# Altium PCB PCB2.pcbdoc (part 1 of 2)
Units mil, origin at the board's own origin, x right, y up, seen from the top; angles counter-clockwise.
Board outline 4275 x 4381.77 mil, 2 copper layers (Top Layer, Bottom Layer); 56 components, 70 nets, 265 pads, 133 vias.
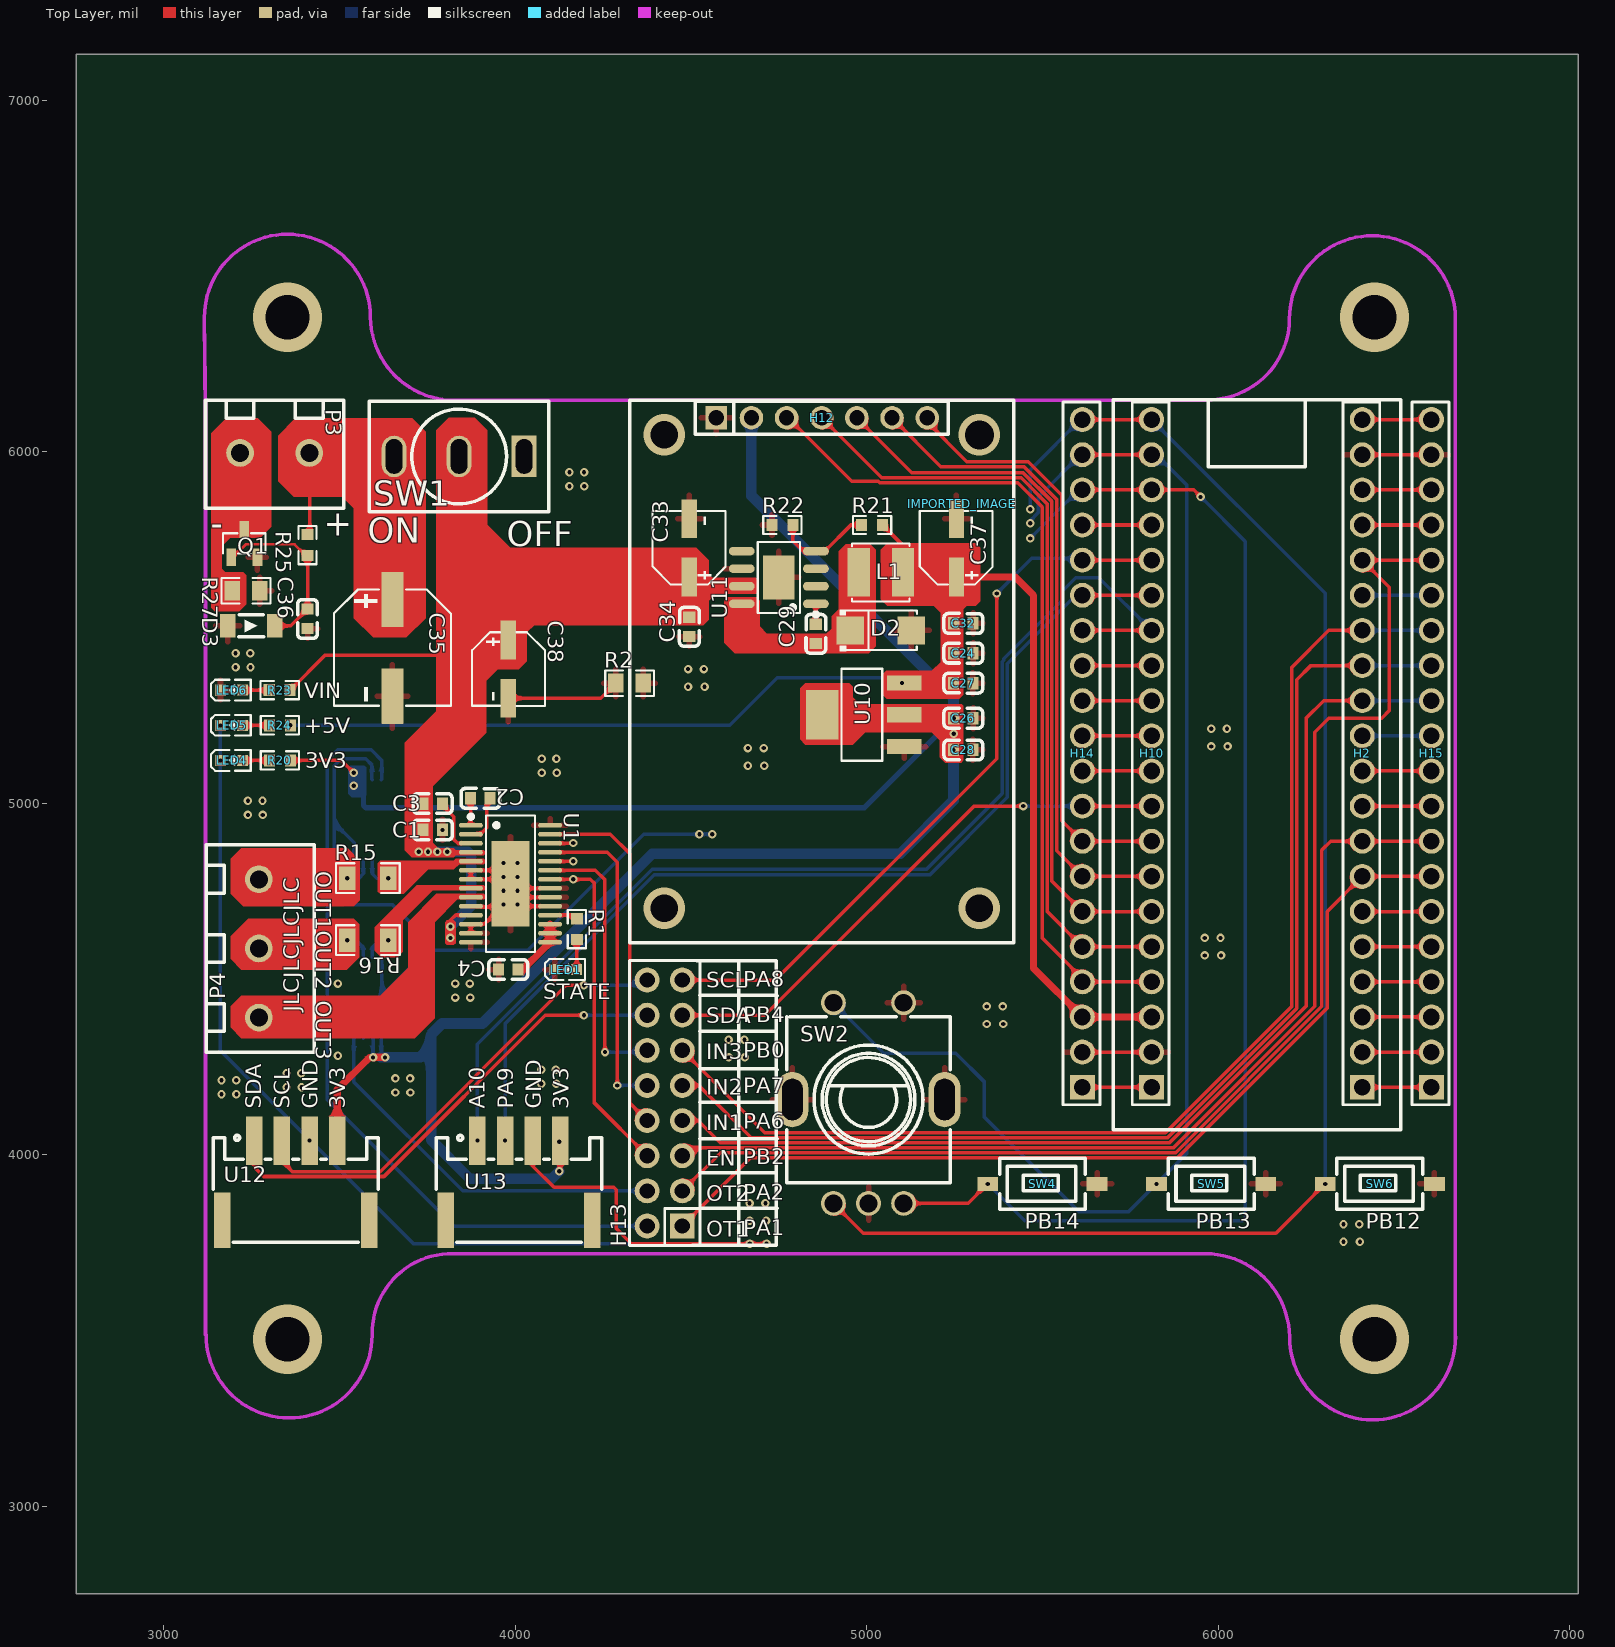
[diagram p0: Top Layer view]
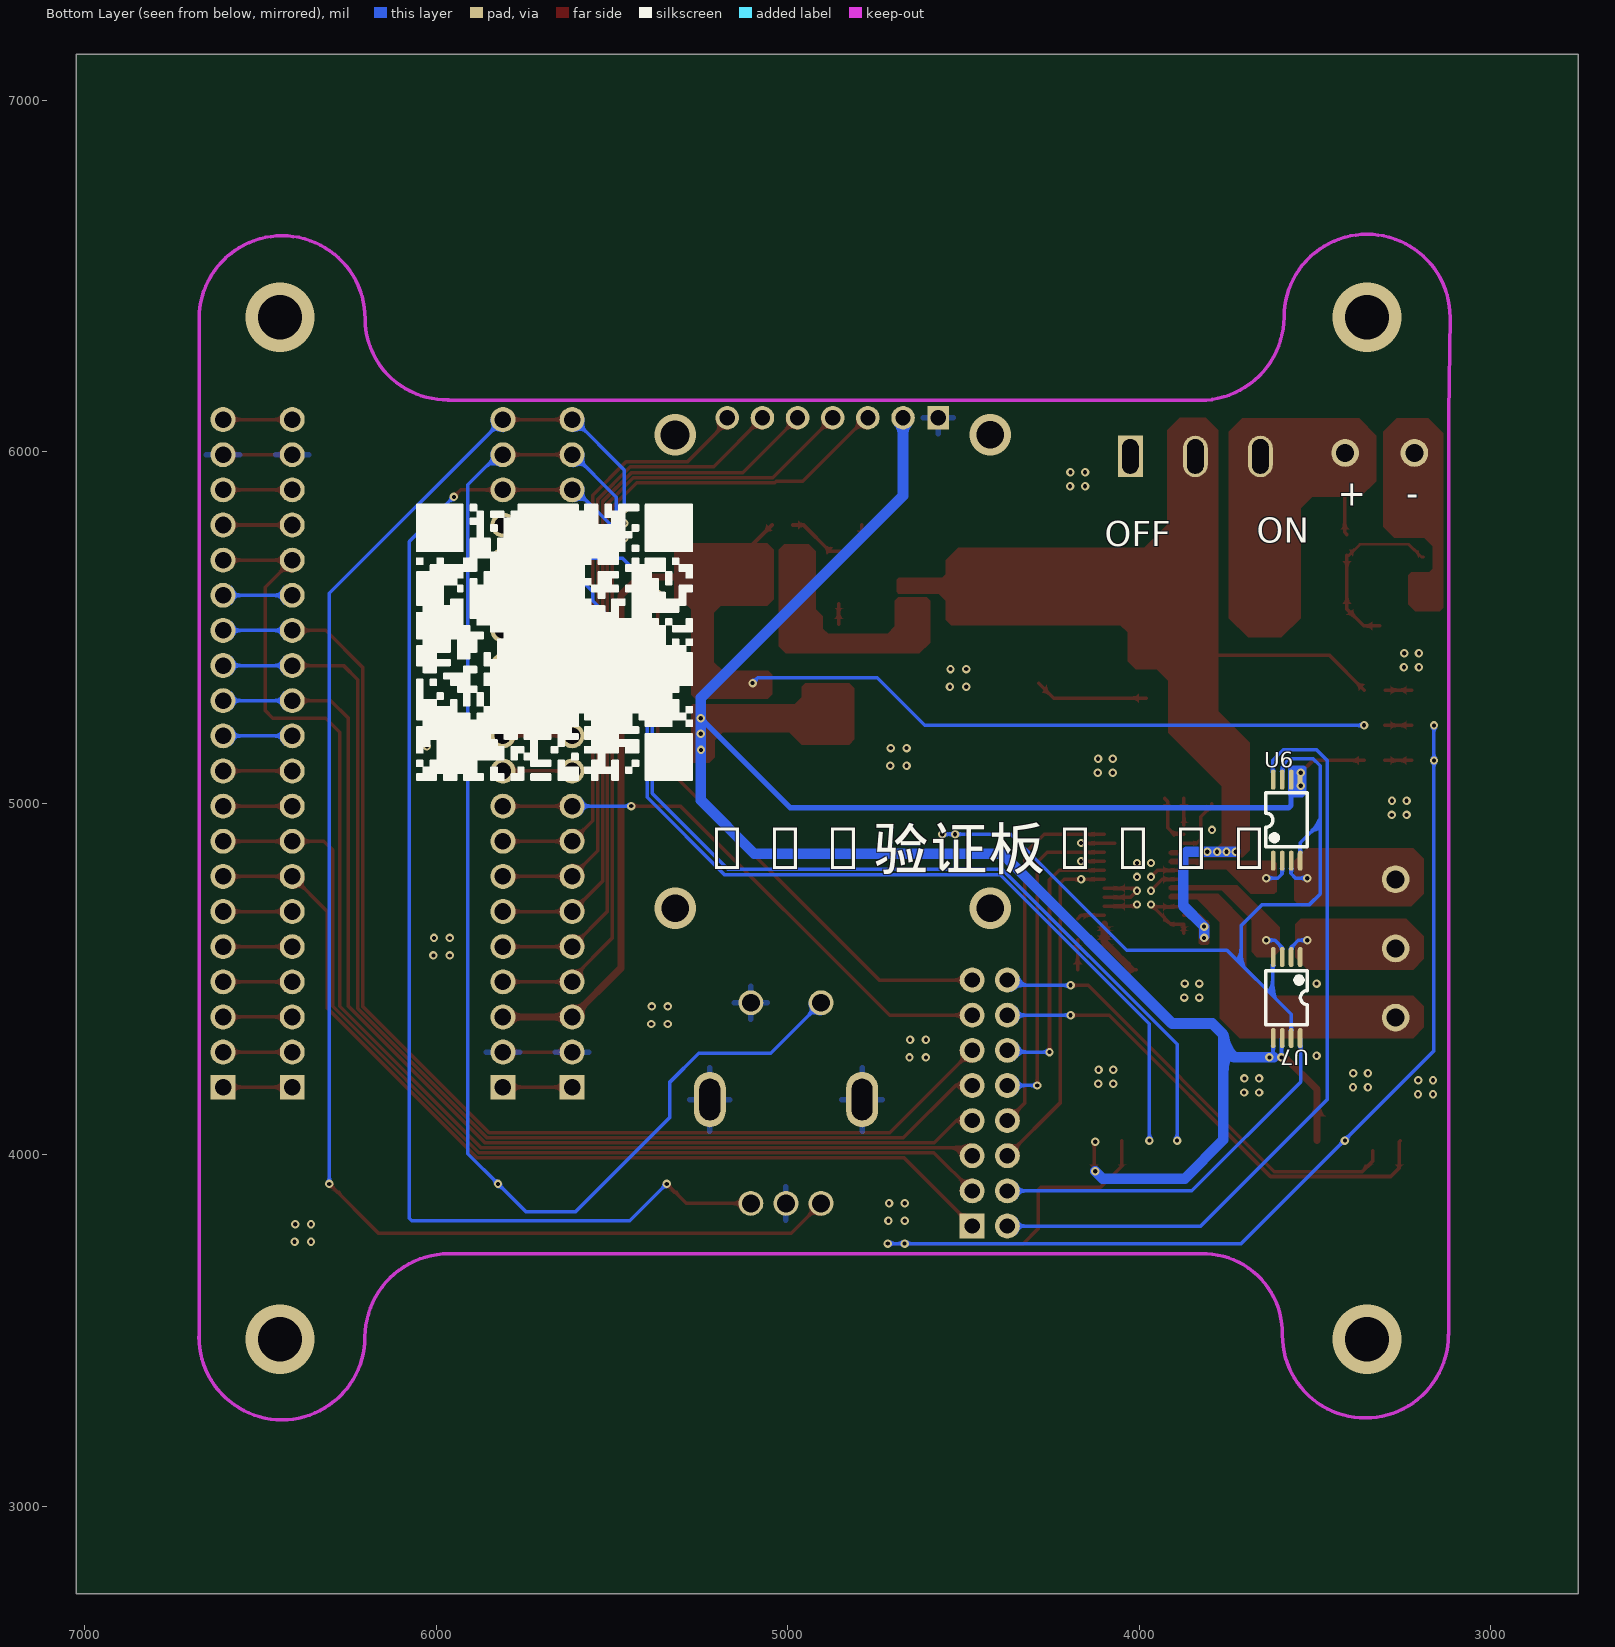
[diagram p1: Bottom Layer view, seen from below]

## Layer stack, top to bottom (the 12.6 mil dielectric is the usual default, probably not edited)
Top Layer: signal copper (thickness not stored)
Dielectric: dielectric 12.6, FR-4, Dk 4.8
Bottom Layer: signal copper (thickness not stored)

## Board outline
7025,2750 2750,2750 2750,7131.77 7025,7131.77

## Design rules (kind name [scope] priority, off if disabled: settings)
Clearance copperThickness1oz [All] p1: gap=7 ignorepadtopadclearanceinfootprint=FALSE except(4: Track-Track; 6: Track-SMDPad SMDPad-SMDPad Track-THPad SMDPad-THPad THPad-THPad Track-Via SMDPad-Via THPad-Via Via-Via SMDPad-Fill THPad-Fill Via-Fill Fill-Fill Track-Region SMDPad-Region THPad-Region Via-Region Region-Region Track-Poly SMDPad-Poly THPad-Poly Via-Poly Fill-Poly Region-Poly Poly-Poly Track-Text SMDPad-Text THPad-Text Via-Text Fill-Text Region-Text Poly-Text Text-Text; 6.9: Track-Hole SMDPad-Hole THPad-Hole Via-Hole Fill-Hole Region-Hole Poly-Hole Text-Hole Sheet-Hole; 11.8: Track-Fill Fill-Region Track-Sheet SMDPad-Sheet THPad-Sheet Via-Sheet Fill-Sheet Region-Sheet Poly-Sheet Text-Sheet)
Clearance copperThickness2oz [All] p1: gap=7 ignorepadtopadclearanceinfootprint=FALSE except(6: Track-SMDPad SMDPad-SMDPad Track-THPad SMDPad-THPad THPad-THPad Track-Via SMDPad-Via THPad-Via Via-Via SMDPad-Fill THPad-Fill Via-Fill Fill-Fill Track-Region SMDPad-Region THPad-Region Via-Region Region-Region Track-Poly SMDPad-Poly THPad-Poly Via-Poly Fill-Poly Region-Poly Poly-Poly Track-Text SMDPad-Text THPad-Text Via-Text Fill-Text Region-Text Poly-Text Text-Text; 6.9: Track-Hole SMDPad-Hole THPad-Hole Via-Hole Fill-Hole Region-Hole Poly-Hole Text-Hole Sheet-Hole; 8: Track-Track; 11.8: Track-Fill Fill-Region Track-Sheet SMDPad-Sheet THPad-Sheet Via-Sheet Fill-Sheet Region-Sheet Poly-Sheet Text-Sheet)
DiffPairsRouting differentialPair [All] p1: maxuncoupledlength=10 maxlimit=5.9843 mostfreqgap=5.9843 toplayer_minwidth=5 toplayer_prefwidth=10 toplayer_maxwidth=100 bottomlayer_minwidth=5 bottomlayer_prefwidth=10 bottomlayer_maxwidth=100
PasteMaskExpansion pasteMaskExpansion [All] p1:
PlaneConnect innerPlane [All] p1: planeconnectstyle=Relief reliefexpansion=20 reliefentries=4 reliefconductorwidth=10 reliefairgap=10
PolygonConnect copperRegion [All] p1: connectstyle=Relief reliefentries=4 reliefconductorwidth=15.748 polygonreliefangle="90 Angle" airgapwidth=11.811
RoutingVias viaSize [All] p1: viastyle="Through Hole" holewidth=12.0078 minholewidth=11.811 maxholewidth=248.0314 width=24.0158 minwidth=19.685 maxwidth=393.7008
SolderMaskExpansion solderMaskExpansion [All] p1: useseparateexpansions=TRUE expansion=2.0079 expansionbottom=2.0079
Width copperThickness1oz [All] p1: maxlimit=100 minlimit=5 preferedwidth=10
Width copperThickness2oz [All] p1: maxlimit=100 minlimit=8 preferedwidth=10

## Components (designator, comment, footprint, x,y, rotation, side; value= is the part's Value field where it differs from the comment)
C1 "0603B104K500NT" C0603 3765.03,4924.12 r180 top
C2 "CC0603KRX7R9BB103" C0603 3900.03,5014.12 r180 top
C3 "0603B104K500NT" C0603 3765.03,4999.12 r0 top
C4 "CL10B474KA8NNNC" C0603 3980,4526.77 r0 top
C24 "100nF" C0603 5275,5426.77 r0 top
C26 "100nF" C0603 5275,5241.77 r0 top
C27 "22uF" C0603 5274.39,5341.77 r180 top
C28 "22uF" C0603 5274.39,5151.77 r180 top
C29 "CAP_0603" C0603 4855,5481.77 r270 top
C32 "0.1u" C0603 5275,5511.77 r0 top
C33 "FVH016ADA470M0554" CAP-SMD_BD5.0-L5.3-W5.3-FD 4495,5726.77 r90 top
C34 "0.1u" C0603 4495,5501.77 r270 top
C35 "LZ1C471M0810" CAP-SMD_BD8.0-L8.3-W8.3-LS9.3-FD-2 3650,5441.77 r270 top
C36 "CAP_0603" C0603 3408.49,5524.64 r90 top
C37 "FVH016ADA470M0554" CAP-SMD_BD5.0-L5.3-W5.3-FD 5255,5726.77 r90 top
C38 "FVH016ADA470M0554" CAP-SMD_BD5.0-L5.3-W5.3-FD 3980,5381.77 r270 top
D2 "SS36" SMA_L4.3-W2.6-LS5.2-RD 5040,5491.77 r0 top
D3 "ZMM12_C707203" LL-34_L3.5-W1.5-RD 3248.49,5504.64 r180 top
H2 "HDR-M_2.54_1x20P" HDR-TH_20P-P2.54-V-M-1 6410,5141.77 r90 top
H10 "HDR-M_2.54_1x20P" HDR-TH_20P-P2.54-V-M-1 5810.39,5141.77 r90 top
H12 "HDR-F_2.54_1x7P" HDR-TH_7P-P2.54-V-F 4871.85,6096.77 r0 top
H13 "HDR-F_2.54_2x8" HDR-TH_16P-P2.54-V-F-R2-C8-S2.54-1 4425,4146.77 r90 top
H14 "HDR-M_2.54_1x20P" HDR-TH_20P-P2.54-V-M-1 5613.54,5141.77 r90 top
H15 "HDR-M_2.54_1x20P" HDR-TH_20P-P2.54-V-M-1 6606.85,5141.77 r90 top
IMPORTED_IMAGE "IMPORTED_IMAGE" IMPORTED_IMAGE 5270,5851.77 r0 top
L1 "SWPA4018S100MT" IND-SMD_L4.0-W4.0 5040,5656.77 r0 top
LED1 "LED_0603-R" LED_0603 4145,4526.77 r0 top
LED4 "LED_0603-R" LED_0603 3194.34,5121.97 r0 top
LED5 "LED_0603-R" LED_0603 3194.34,5221.97 r0 top
LED6 "LED_0603-R" LED_0603 3194.34,5321.97 r0 top
P3 "WJ126V-5.0-2P" conn-th_wj126v-5.0-2p 3315,5996.77 r270 top
P4 "WJ126V-5.0-3P" CONN-TH_3P-P5.00_WJ126V-5.0-3P 3270,4586.77 r90 top
Q1 "AO3400A_C347475" SOT-23-3_L2.9-W1.3-P1.90-LS2.4-BR 3228.49,5739.64 r270 top
R1 "Res_0603" R0603 4175,4641.77 r270 top
R2 "0" R0805 4325,5341.77 r0 top
R15 "0.01" R1206 3580,4786.77 r0 top
R16 "0.01" R1206 3580,4610.15 r180 top
R20 "Res_0603" R0603 3330,5121.77 r180 top
R21 "Res_0603" R0603 5015,5791.77 r0 top
R22 "Res_0603" R0603 4760,5791.77 r0 top
R23 "Res_0603" R0603 3329.34,5321.97 r180 top
R24 "Res_0603" R0603 3330,5221.77 r180 top
R25 "Res_0603" R0603 3408.49,5734.64 r90 top
R27 "Res_0805" R0805 3233.49,5604.64 r0 top
SW1 "MT-0-103-A101-M200-RS" SW-TH_MT-0-103-A101-M200-RS 3840,5986.77 r180 top
SW2 "EC11E15244G1" SW-TH_EC11E15244G1 5005,4146.77 r0 top
SW4 "Key_SMD_3.6x6.1x2.5" Key_SMD_3.6x6.1x2.5 5500,3916.77 r0 top
SW5 "Key_SMD_3.6x6.1x2.5" Key_SMD_3.6x6.1x2.5 5980,3916.77 r0 top
SW6 "Key_SMD_3.6x6.1x2.5" Key_SMD_3.6x6.1x2.5 6460,3916.77 r0 top
U1 "DRV8313PWPR" HTSSOP-28_L9.8-W4.5-P0.65-LS6.6-BL-EP 3986.09,4770.8 r270 top
U6 "INA240A2PWR" TSSOP-8_L4.4-W3.0-P0.65-LS6.4-BL 3580,4951.77 r180 bottom
U7 "INA240A2PWR" TSSOP-8_L4.4-W3.0-P0.65-LS6.4-BL 3580,4446.77 r0 bottom
U10 "AMS1117-3.3" SOT-223-3_L6.5-W3.4-P2.30-LS7.0-BR 4990,5251.77 r0 top
U11 "TPS5430DDA" ESOP-8_L4.9-W3.9-P1.27-LS6.0-BL-EP-2 4749.6,5642.45 r90 top
U12 "XY-PH2.0-4A61" CONN-SMD_4P-P2.00_XYECONN_XY-PH2.0-4A61 3375,3926.77 r0 top
U13 "XY-PH2.0-4A61" CONN-SMD_4P-P2.00_XYECONN_XY-PH2.0-4A61 4010,3926.77 r0 top

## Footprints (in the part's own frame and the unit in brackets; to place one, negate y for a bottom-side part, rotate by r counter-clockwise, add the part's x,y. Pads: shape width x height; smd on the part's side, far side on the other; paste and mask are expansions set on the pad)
C0603 [mm]
  rect 0.8x0.9 smd: 1(-0.7,0) 2(0.7,0)
  silkscreen extent -1.41,-0.71 1.39,0.72
CAP-SMD_BD5.0-L5.3-W5.3-FD [mm]
  rect 2.8x1.1 smd: 1(-2.1,0) 2(2.1,0)
  silkscreen extent -2.66,-2.62 2.66,2.65
CAP-SMD_BD8.0-L8.3-W8.3-LS9.3-FD-2 [mm]
  rect 4x1.6 smd: 1(-3.5,0) 2(3.5,0)
  silkscreen extent -4.23,-4.23 4.18,4.23
CONN-SMD_4P-P2.00_XYECONN_XY-PH2.0-4A61 [mm]
  rect 1.2x3.5 smd: 1(-3,2.875) 2(-1,2.875) 3(1,2.875) 4(3,2.875)
  rect 1.2x4 smd: 5(5.3,-2.875) 6(-5.3,-2.875)
  silkscreen extent -5.98,-4.47 5.97,3.25
CONN-TH_3P-P5.00_WJ126V-5.0-3P [mm]
  round 2 hole 1.3: 1(5,0) 2(-0.001,0) 3(-5,0)
  silkscreen extent -7.5,-4 7.5,3.8
conn-th_wj126v-5.0-2p [mm]
  round 2 hole 1.3: 1(0,2.501) 2(0,-2.501)
  silkscreen extent -3.8,-5 4,5
ESOP-8_L4.9-W3.9-P1.27-LS6.0-BL-EP-2 [mm]
  oval 0.63x1.865 smd: 1(-1.905,-2.683) 2(-0.635,-2.683) 3(0.635,-2.683) 4(1.905,-2.683) 5(1.905,2.682) 6(0.635,2.682) 7(-0.635,2.682) 8(-1.905,2.682)
  rect 3.15x2.26 smd: 9(0,0)
  silkscreen extent -2.82,-2.83 2.58,1.52
HDR-TH_7P-P2.54-V-F [mm]
  rect 1.575x1.7 hole 1.1: 1(-7.62,0)
  round 1.7 hole 1.1: 2(-5.08,0) 3(-2.54,0) 4(0,0) 5(2.54,0) 6(5.08,0) 7(7.62,0)
  silkscreen extent -9.13,-1.2 9.13,1.2
HDR-TH_16P-P2.54-V-F-R2-C8-S2.54-1 [mm]
  rect 1.8x1.8 hole 1.1: 1(-8.89,-1.27)
  round 1.8 hole 1.1: 2(-8.89,1.27) 3(-6.35,-1.27) 4(-6.35,1.27) 5(-3.81,-1.27) 6(-3.81,1.27) 7(-1.27,-1.27) 8(-1.27,1.27) 9(1.27,-1.27) 10(1.27,1.27) 11(3.81,-1.27) 12(3.81,1.27) 13(6.35,-1.27) 14(6.35,1.27) 15(8.89,-1.27) 16(8.89,1.27)
  silkscreen extent -10.3,-2.54 10.3,2.54
HDR-TH_20P-P2.54-V-M-1 [mil]
  rect 70.9x70.9 hole 47.2: 1(-950,0)
  round 70.9 hole 47.2: 2(-850,0) 3(-750,0) 4(-650,0) 5(-550,0) 6(-450,0) 7(-350,0) 8(-250,0) 9(-150,0) 10(-50,0) 11(50,0) 12(150,0) 13(250,0) 14(350,0) 15(450,0) 16(550,0) 17(650,0) 18(750,0) 19(850,0) 20(950,0)
  silkscreen extent -1000,-50 1000,55
HTSSOP-28_L9.8-W4.5-P0.65-LS6.6-BL-EP [mm]
  oval 0.343x1.731 smd: 1(-4.225,-2.866) 2(-3.575,-2.866) 3(-2.925,-2.866) 4(-2.275,-2.866) 5(-1.625,-2.866) 6(-0.975,-2.866) 7(-0.325,-2.866) 8(0.325,-2.866) 9(0.975,-2.866) 10(1.625,-2.866) 11(2.275,-2.866) 12(2.925,-2.866) 13(3.575,-2.866) 14(4.225,-2.866) 15(4.225,2.866) 16(3.575,2.866) 17(2.925,2.866) 18(2.275,2.866) 19(1.625,2.866) 20(0.975,2.866) 21(0.325,2.866) 22(-0.325,2.866) 23(-0.975,2.866) 24(-1.625,2.866) 25(-2.275,2.866) 26(-2.925,2.866) 27(-3.575,2.866) 28(-4.225,2.866)
  rect 6.2x2.75 smd: 29(0,0)
  silkscreen extent -5,-3.02 4.93,1.77
IMPORTED_IMAGE [mil]
IND-SMD_L4.0-W4.0 [mm]
  rect 1.6x3.5 smd: 1(-1.6,0) 2(1.6,0)
  silkscreen extent -2.08,-2.1 2.08,2.1
Key_SMD_3.6x6.1x2.5 [mil]
  rect 59.1x39.4 smd: 1(-155.5,0) 2(155.5,0)
  silkscreen extent -122,-73 122,73
LED_0603 [mil]
  rect 31.5x31.5 smd: 1(-33.5,-0.4) 2(29.5,-0.2)
  silkscreen extent -61,-30 53,30
LL-34_L3.5-W1.5-RD [mm]
  rect 1.1x1.7 smd: 1(-1.7,0) 2(1.7,0)
  silkscreen extent -0.9,-0.8 0.9,0.8
R0603 [mil]
  rect 31.75x34.02 smd: 1(-29.66,0) 2(29.66,0)
  silkscreen extent -55,-26 55,26
R0805 [mm]
  rect 1.133x1.377 smd: 1(-1,0) 2(1,0)
  silkscreen extent -1.76,-0.92 1.76,0.92
R1206 [mil]
  rect 47.54x66.97 smd: 1(-58.22,0) 2(58.22,0)
  silkscreen extent -91,-42 91,42
SMA_L4.3-W2.6-LS5.2-RD [mm]
  rect 2x2 smd: 1(-2.2,0) 2(2.2,0)
  silkscreen extent -2.98,-1.5 2.6,1.5
SOT-23-3_L2.9-W1.3-P1.90-LS2.4-BR [mm]
  rect 1.25x0.7 smd: 1(1,-0.95) 2(1,0.95) 3(-1,0)
  silkscreen extent -0.73,-1.53 0.73,1.53
SOT-223-3_L6.5-W3.4-P2.30-LS7.0-BR [mm]
  rect 2.5x1.1 smd: 1(2.97,-2.3) 2(2.97,0) 3(2.97,2.3)
  rect 2.34x3.6 smd: 4(-2.97,0)
  silkscreen extent -1.57,-3.33 1.37,3.33
SW-TH_EC11E15244G1 [mm]
  oval 2.3x4 hole 1.5 slot 3 at 90 deg: 6(5.5,0.25) 7(-5.5,0.25)
  round 1.8 hole 1.3: A(-2.54,-7.25) B(2.54,-7.25) C(0,-7.25) D(-2.54,7.25) E(2.54,7.25)
  silkscreen extent -5.9,-5.75 5.9,6.25
SW-TH_MT-0-103-A101-M200-RS [mm]
  rect 1.8x3 hole 1.2 slot 2.5 at 90 deg: 1(-4.7,0)
  oval 1.8x3 hole 1.2 slot 2.5 at 90 deg: 2(0,0) 3(4.7,0)
  silkscreen extent -6.48,-4 6.5,4
TSSOP-8_L4.4-W3.0-P0.65-LS6.4-BL [mil]
  oval 13.9x57.24 smd: 1(-38.39,-115.24) 2(-12.79,-115.24) 3(12.8,-115.24) 4(38.39,-115.24) 5(38.39,115.24) 6(12.8,115.24) 7(-12.79,115.24) 8(-38.39,115.24)
  silkscreen extent -59,-76 59,77

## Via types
v1: diameter 24.02, hole 12.01, Top Layer to Bottom Layer, 117 vias
v2: diameter 23.62, hole 11.81, Top Layer to Bottom Layer, 8 vias
v3: diameter 196.85, hole 125.98, Top Layer to Bottom Layer, 4 vias
v4: diameter 118.11, hole 78.74, Top Layer to Bottom Layer, 3 vias
v5: diameter 118.11, hole 82.68, Top Layer to Bottom Layer, 1 vias

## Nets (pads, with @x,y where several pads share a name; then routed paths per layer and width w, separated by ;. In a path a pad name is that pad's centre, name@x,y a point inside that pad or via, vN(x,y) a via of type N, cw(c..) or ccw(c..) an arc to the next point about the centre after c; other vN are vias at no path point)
$1N2058: C4.2 U1.15 U1.16 U1.17 | length 174.7
  Top Layer w10: C4.2@4007.56,4526.77 C4.2@4021.22,4526.77
  Top Layer w20: C4.2@4021.22,4526.77 U1.15@4098.91,4604.46 U1.16@4098.91,4630.05 U1.17@4098.91,4655.64
$1N2061: C2.2 U1.1 | length 77.3
  Top Layer w10: C2.2@3872.47,5014.12 3872.47,4937.93 U1.1@3873.26,4937.14
$1N2062: C2.1 U1.2 | length 140.8
  Top Layer w10: U1.2@3873.26,4911.55 3900.09,4911.55 3918.33,4929.8 3918.33,5004.86 C2.1@3927.59,5014.12
$1N2063: C3.2 U1.3 | length 168.5
  Top Layer w10: C3.2@3792.59,4999.12 3792.59,4994.12 3825,4961.72 3825,4896.77 3835.81,4885.96 U1.3@3873.26,4885.96
$1N2072: R1.1 U1.18 | length 80.1
  Top Layer w10: U1.18@4098.91,4681.23 4165.2,4681.23 R1.1@4175,4671.43
$1N2073: LED1.2 R1.2 | length 85.7
  Top Layer w10: LED1.2@4174.5,4526.57 4175,4527.07 R1.2@4175,4612.11
$1N2080: LED4.2 R20.2 | length 76.5
  Top Layer w10: LED4.2@3223.84,5121.77 R20.2@3300.34,5121.77
$1N2087: C29.1 U11.1 | length 58.2
  Top Layer w10: C29.1@4855,5509.33 4855,5567.23 U11.1@4855.21,5567.44
$1N2088: R21.1 R22.2 U11.4 | length 283.4
  Top Layer w10: R22.2@4789.66,5791.77 4789.66,5747.11 4819.33,5717.44 U11.4@4855.21,5717.44 4880.67,5717.44 4955,5791.77 R21.1@4985.34,5791.77
$1N2090: P3.2 Q1.3 R27.1
$1N2099: LED6.2 R23.2 | length 75.9
  Top Layer w10: LED6.2@3223.84,5321.77 3299.48,5321.77 R23.2@3299.68,5321.97
$1N2103: LED5.2 R24.2 | length 76.5
  Top Layer w10: LED5.2@3223.84,5221.77 R24.2@3300.34,5221.77
$1N2889: C29.2 D2.1 L1.1 U11.8
$1N3381: C36.2 D3.1 Q1.1 R25.1 | length 511.2
  Top Layer w8: Q1.1@3191.09,5700.27 3196.09,5700.27 3232.6,5736.77 3371.7,5736.77 3403.49,5704.98 R25.1@3408.49,5704.98
  Top Layer w10: D3.1@3315.42,5504.64 3360.93,5504.64 C36.2@3408.49,5552.2 R25.1@3408.49,5704.98
AS5600_SCL: H13.16 U12.2 | length 1307
  Top Layer w10: U12.2@3335,4010.6 3335,3981.77 3365,3951.77 3615,3951.77 4145,4481.77 v1(4195,4481.77)
  Bottom Layer w10: v1(4195,4481.77) 4360,4481.77 H13.16@4375,4496.77
AS5600_SDA: H13.14 U12.1 | length 1394.5
  Top Layer w10: U12.1@3256.89,4039.96 3260,4036.85 3260,3961.77 3284.02,3937.76 3625.98,3937.76 4085,4396.77 v1(4195,4396.77)
  Bottom Layer w10: v1(4195,4396.77) H13.14@4375,4396.77
GND: C24.2 C26.2 C27.1 C28.1 C32.2 C33.2 C34.2 C37.2 D2.2 H2.19 H10.2 H12.1 H14.2 H15.19 LED4.1 LED5.1 R2.2 R22.1 SW2.6 SW2.7 SW2.C SW2.E SW4.2 SW5.2 SW6.2 U6.4 U6.7 U7.4 U7.7 U10.1 U11.6 U11.9 U12.3 U13.3 | length 6411.9
  Top Layer w10: U13.3@4049.37,4039.97 4049.37,3967.4 4110,3906.77 4280,3906.77 4287.07,3899.7 4287.07,3789.7 4330,3746.77 v1(4667.27,3746.77) v1(4715,3746.77) ; H14.2@5613.54,4291.77 H10.2@5810.39,4291.77 ; H2.19@6410,5991.77 H15.19@6606.85,5991.77
  Bottom Layer w10: v1(3160.84,5221.57) v1(3160.84,5121.52) 3160.84,4295.94 3710,3746.77 v1(4667.27,3746.77) v1(4715,3746.77) ; U6.4@3541.61,4836.53 3541.61,4887.85 3485,4944.46 ; U7.7@3567.21,4331.53 3567.21,4398.98 3620,4451.77 ; U6.7@3592.79,5067.01 3591.81,5067.99 3591.81,5108.74 3573.77,5126.77 3505,5126.77 3485,5106.77 3485,4944.46 ; U7.4@3618.39,4562.01 3620,4560.4 3620,4451.77 ; v1(4560,4911.77) v1(4523.82,4911.77) 4365,4911.77 4035,4581.77 3750,4581.77 3710,4541.77 ; 3485,4944.46 3485,4741.77 3515,4711.77 3650,4711.77 3710,4651.77 3710,4541.77 ; 3620,4451.77 3710,4541.77
  other v1: 6356.65,3751.77 6403.35,3751.77 6356.65,3801.77 6401.65,3801.77 4666.65,3811.77 4713.35,3811.77 4666.65,3861.77 4711.65,3861.77 3414.37,4039.97 4606.65,4276.77 4653.35,4276.77 4606.65,4326.77 4651.65,4326.77 5341.65,4371.77 5388.35,4371.77 5341.65,4421.77 5386.65,4421.77 5961.65,4566.77 6008.35,4566.77 5961.65,4616.77 6006.65,4616.77 4661.65,5106.77 4708.35,5106.77 4661.65,5156.77 4706.65,5156.77 5980,5161.77 6026.7,5161.77 5980,5211.77 6025,5211.77 4491.65,5331.77 4538.35,5331.77 4491.65,5381.77 4536.65,5381.77
M0_EN: H13.6 U1.22 U1.24 U1.26 | length 1130.4
  Top Layer w10: U1.26@4069.19,4885.96 U1.26@4098.91,4885.96 4164.19,4885.96 v1(4165,4886.77) ; U1.22@4098.91,4783.59 4164.84,4783.59 v1(4165,4783.44) 4213.34,4783.44 4225,4771.77 4225,4146.77 H13.6@4375,3996.77 ; U1.24@4098.91,4834.78 4164.84,4834.78 v1(4165,4834.94)
M0_IN1: H13.8 U1.27 | length 1029.5
  Top Layer w10: U1.27@4098.91,4911.55 4270.22,4911.55 4325,4856.77 4325,4146.77 H13.8@4375,4096.77
M0_IN2: H13.10 U1.25 | length 922.9
  Top Layer w10: U1.25@4098.91,4860.37 4261.4,4860.37 4290,4831.77 v1(4290,4196.77)
  Bottom Layer w10: v1(4290,4196.77) H13.10@4375,4196.77
M0_IN3: H13.12 U1.23 | length 779.5
  Top Layer w10: U1.23@4098.91,4809.19 4227.58,4809.19 4255,4781.77 v1(4255,4291.77)
  Bottom Layer w10: v1(4255,4291.77) 4370,4291.77 H13.12@4375,4296.77
M0_OUT1_CS: H13.2 U6.8 | length 2259.4
  Bottom Layer w10: U6.8@3618.39,5067.01 3620,5068.62 3620,5121.77 3590,5151.77 3495,5151.77 3465,5121.77 3465,4156.77 3825,3796.77 H13.2@4375,3796.77
M0_OUT1_N: P4.1 R15.1 U6.3 | length 88
  Bottom Layer w10: v1(3521.78,4786.77) 3555,4786.77 3567.2,4798.97 U6.3@3567.2,4836.53
M0_OUT1_P: R15.2 U1.5 U6.2 | length 88
  Bottom Layer w10: U6.2@3592.79,4836.53 3592.79,4798.98 3605,4786.77 v1(3638.22,4786.77)
M0_OUT2_CS: H13.4 U7.8 | length 1088.8
  Bottom Layer w10: U7.8@3541.61,4331.53 3540,4329.92 3540,4206.77 3850,3896.77 H13.4@4375,3896.77
M0_OUT2_N: P4.2 R16.2 U7.2 | length 81.5
  Bottom Layer w10: v1(3521.78,4610.15) 3546.62,4610.15 3567.21,4589.56 U7.2@3567.21,4562.01
M0_OUT2_P: R16.1 U1.8 U7.3 | length 81.5
  Bottom Layer w10: U7.3@3592.8,4562.01 3592.8,4589.57 3613.38,4610.15 v1(3638.22,4610.15)
M0_OUT3: P4.3 U1.9
MCU_3V3: H10.1 H14.1 | length 196.9
  Top Layer w10: H14.1@5613.54,4191.77 H10.1@5810.39,4191.77
MCU_3V3_1: H2.18 H15.18 | length 196.9
  Top Layer w10: H2.18@6410,5891.77 H15.18@6606.85,5891.77
MCU_5V: H2.20 H15.20 | length 196.9
  Top Layer w10: H2.20@6410,6091.77 H15.20@6606.85,6091.77
NRST: H2.5 H15.5 | length 196.9
  Top Layer w10: H2.5@6410,4591.77 H15.5@6606.85,4591.77
PA0: H2.6 H15.6 | length 196.9
  Top Layer w10: H2.6@6410,4691.77 H15.6@6606.85,4691.77
PA1: H2.7 H13.1 H15.7 | length 2704.9
  Top Layer w10: H13.1@4475,3796.77 4669.92,3991.7 5884.56,3991.7 6310,4417.13 6310,4691.77 H2.7@6410,4791.77 H15.7@6606.85,4791.77
PA2: H2.8 H13.3 H15.8 | length 2804.6
  Top Layer w10: H13.3@4475,3896.77 4583.94,4005.71 5878.76,4005.71 6295,4421.95 6295,4866.77 6320,4891.77 H2.8@6410,4891.77 H15.8@6606.85,4891.77
PA3: H2.9 H15.9 | length 196.9
  Top Layer w10: H2.9@6410,4991.77 H15.9@6606.85,4991.77
PA4: H2.10 H15.10 | length 196.9
  Top Layer w10: H2.10@6410,5091.77 H15.10@6606.85,5091.77
PA5: H2.11 H15.11 | length 196.9
  Bottom Layer w10: H2.11@6410,5191.77 H15.11@6606.85,5191.77
PA6: H2.12 H13.7 H15.12 | length 3159.2
  Top Layer w10: H13.7@4475,4096.77 4520,4096.77 4583.03,4033.74 5861.61,4033.74 6250,4422.13 6250,5241.77 6300,5291.77 H2.12@6410,5291.77
  Bottom Layer w10: H2.12@6410,5291.77 H15.12@6606.85,5291.77
PA7: H2.13 H13.9 H15.13 | length 3298.5
  Top Layer w10: H13.9@4475,4196.77 4522.26,4196.77 4671.27,4047.76 5855.81,4047.76 6224.02,4415.97 6224.02,5351.77 6264.02,5391.77 H2.13@6410,5391.77
  Bottom Layer w10: H2.13@6410,5391.77 H15.13@6606.85,5391.77
PA8: H10.16 H13.15 H14.16 | length 2107.8
  Top Layer w10: H13.15@4475,4496.77 4740,4496.77 5370,5126.77 v1(5370,5596.77) ; H14.16@5613.54,5691.77 H10.16@5810.39,5691.77
  Bottom Layer w10: v1(5370,5596.77) 5470,5696.77 H14.16@5613.54,5696.77
PA9: H10.15 H14.15 U13.2 | length 2899.9
  Top Layer w10: H14.15@5613.54,5591.77 H10.15@5810.39,5591.77
  Bottom Layer w10: v1(3970.63,4039.97) 3970.63,4372.41 4395,4796.77 5180,4796.77 5400,5016.77 5400,5396.77 5595,5591.77 H14.15@5613.54,5591.77
PA10: H10.14 H14.14 U13.1 | length 3238.6
  Top Layer w10: H14.14@5613.54,5491.77 H10.14@5810.39,5491.77
  Bottom Layer w10: v1(3891.89,4039.96) 3891.89,4313.67 4390,4811.77 5170,4811.77 5385.98,5027.76 5385.98,5402.58 5390,5406.6 5390,5410.79 5555,5575.79 5555,5601.77 5595,5641.77 5660.39,5641.77 H10.14@5810.39,5491.77
PA11: H10.13 H14.13 | length 196.9
  Top Layer w10: H14.13@5613.54,5391.77 H10.13@5810.39,5391.77
PA12: H10.12 H14.12 | length 196.9
  Top Layer w10: H14.12@5613.54,5291.77 H10.12@5810.39,5291.77
PA15: H10.11 H14.11 | length 196.9
  Top Layer w10: H14.11@5613.54,5191.77 H10.11@5810.39,5191.77
PB0: H2.14 H13.11 H15.14 | length 3386.8
  Top Layer w10: H13.11@4475,4296.77 4710,4061.77 5850,4061.77 6210,4421.77 6210,5386.77 6315,5491.77 H2.14@6410,5491.77
  Bottom Layer w10: H2.14@6410,5491.77 H15.14@6606.85,5491.77
PB1: H2.15 H15.15 | length 196.9
  Bottom Layer w10: H2.15@6410,5591.77 H15.15@6606.85,5591.77
PB2: H2.16 H13.5 H15.16 | length 3650.5
  Top Layer w10: H13.5@4475,3996.77 4497.95,4019.73 5872.95,4019.73 6275,4421.77 6275,5201.77 6315,5241.77 6465,5241.77 6487.07,5263.85 6487.07,5614.7 H2.16@6410,5691.77 H15.16@6606.85,5691.77
PB3: H10.10 H14.10 | length 196.9
  Top Layer w10: H14.10@5613.54,5091.77 H10.10@5810.39,5091.77
PB4: H10.9 H13.13 H14.9 | length 1581.9
  Top Layer w10: H13.13@4475,4396.77 4710,4396.77 5305,4991.77 v1(5445,4991.77) ; H14.9@5613.54,4991.77 H10.9@5810.39,4991.77
  Bottom Layer w10: v1(5445,4991.77) H14.9@5613.54,4991.77
PB5: H10.8 H12.7 H14.8 | length 1687.3
  Top Layer w10: H12.7@5171.85,6096.77 5171.85,6084.92 5285,5971.77 5460,5971.77 5555,5876.77 5555,4950.32 H14.8@5613.54,4891.77 H10.8@5810.39,4891.77
PB6: H10.7 H12.6 H14.7 | length 1864.9
  Top Layer w10: H12.6@5071.85,6096.77 5210.87,5957.76 5447.59,5957.76 5540.98,5864.36 5540.98,4864.33 H14.7@5613.54,4791.77 H10.7@5810.39,4791.77
PB7: H10.6 H12.5 H14.6 | length 2053.3
  Top Layer w10: H12.5@4971.85,6096.77 5127.78,5940.84 5444.69,5940.84 5526.97,5858.56 5526.97,4778.35 H14.6@5613.54,4691.77 H10.6@5810.39,4691.77
PB8: H10.5 H12.4 H14.5 | length 2241.7
  Top Layer w10: H12.4@4871.85,6096.77 5042.36,5926.26 5439.44,5926.26 5512.95,5852.75 5512.95,4692.36 H14.5@5613.54,4591.77 H10.5@5810.39,4591.77
PB9: H10.4 H12.3 H14.4 | length 2422.7
  Top Layer w10: H12.3@4771.85,6096.77 4776.85,6096.77 4956.85,5916.77 5032.03,5916.77 5036.55,5912.25 5429.52,5912.25 5498.94,5842.84 5498.94,4616.38 H14.4@5613.54,4501.77 ; H14.4@5613.54,4496.77 H14.4@5613.54,4491.77 H10.4@5810.39,4491.77
PB10: H2.17 H15.17 | length 196.9
  Top Layer w10: H2.17@6410,5791.77 H15.17@6606.85,5791.77
PB12: H10.20 H14.20 SW2.A SW6.1 | length 4390.6
  Top Layer w10: SW2.A@4904.99,3861.34 4989.56,3776.77 6164.5,3776.77 v1(6304.5,3916.77) ; H14.20@5613.54,6091.77 H10.20@5810.39,6091.77
  Bottom Layer w10: v1(5465,5836.77) 5465,5948.23 H14.20@5613.54,6096.77 ; H10.20@5810.39,6091.77 6304.5,5597.67 v1(6304.5,3916.77)
PB13: H10.19 H14.19 SW2.D SW5.1 | length 3876.5
  Top Layer w10: H14.19@5613.54,5991.77 H10.19@5810.39,5991.77
  Bottom Layer w10: SW2.D@4904.99,4432.21 5048.36,4288.85 5252.93,4288.85 5335,4206.77 5335,4106.77 5605,3836.77 5744.5,3836.77 v1(5824.5,3916.77) 5910,4002.27 5910,5906.77 5825,5991.77 H10.19@5810.39,5991.77 ; v1(5465,5796.77) 5465,5804.26 5487.99,5827.25 5487.99,5871.22 H14.19@5613.54,5996.77
PB14: H10.18 H14.18 SW2.B SW4.1 | length 3699.6
  Top Layer w10: SW2.B@5104.99,3861.34 5289.06,3861.34 v1(5344.5,3916.77) ; H14.18@5613.54,5891.77 H10.18@5810.39,5891.77 5930,5891.77 v1(5950,5871.77)
  Bottom Layer w10: v1(5344.5,3916.77) 5449.5,3811.77 6070,3811.77 6077.07,3818.85 6077.07,5744.7 v1(5950,5871.77) ; v1(5465,5753.74) H14.18@5608.03,5896.77 ; H14.18@5608.03,5891.77 H14.18@5613.54,5891.77
PB15: H10.17 H14.17 | length 196.9
  Top Layer w10: H14.17@5613.54,5791.77 H10.17@5810.39,5791.77
PC13: H2.2 H15.2 | length 196.9
  Top Layer w10: H2.2@6410,4291.77 H15.2@6606.85,4291.77
PC14: H2.3 H15.3 | length 196.9
  Top Layer w10: H2.3@6410,4391.77 H15.3@6606.85,4391.77
PC15: H2.4 H15.4 | length 196.9
  Top Layer w10: H2.4@6410,4491.77 H15.4@6606.85,4491.77
PGND: C1.1 C4.1 C35.2 C36.1 C38.2 D3.2 LED1.1 LED6.1 Q1.2 R2.1 R27.2 U1.6 U1.7 U1.10 U1.12 U1.13 U1.14 U1.19 U1.20 U1.21 U1.28 U1.29 | length 1076.8
  Top Layer w10: U1.13@3873.26,4630.05 U1.12@3873.26,4655.64 3910.3,4655.64 U1.29@3959.62,4704.96 ; U1.10@3873.26,4704.96 U1.29@3959.62,4704.96 ; v2(3966.4,4711.74) U1.29@3959.62,4704.96 ; v2(3966.4,4751.11) 3933.92,4783.59 U1.7@3873.26,4783.59 U1.6@3873.26,4809.19 3947.69,4809.19 v2(3966.4,4790.48) ; C38.2@3980,5299.09 4242.95,5299.09 R2.1@4285.63,5341.77 ; v2(4005.77,4711.74) 4010.69,4706.82 U1.19@4098.91,4706.82 ; U1.20@4098.91,4732.41 4024.47,4732.41 v2(4005.77,4751.11) 4012.66,4758 U1.21@4098.91,4758
  other v1: 3163.72,4171.77 3206.28,4171.77 3658.72,4176.77 3701.28,4176.77 3348.72,4191.77 3391.28,4191.77 4073.72,4201.77 4116.28,4201.77 3163.72,4211.77 3205.4,4211.77 3658.72,4216.77 3700.4,4216.77 3348.72,4231.77 3390.4,4231.77 4073.72,4241.77 4115.4,4241.77 3495,4281.3 3828.72,4446.77 3871.28,4446.77 3495,4486.77 3828.72,4486.77 3870.4,4486.77 3792.59,4924.12 3238.72,4966.77 3281.28,4966.77 3238.72,5006.77 3280.4,5006.77 4075,5086.77 4117.56,5086.77 4075,5126.77 4116.68,5126.77 3203.72,5386.77 3246.28,5386.77 3203.72,5426.77 3245.4,5426.77 4153.72,5901.77 4196.28,5901.77 4153.72,5941.77 4195.4,5941.77
  other v2: 4005.77,4790.48 3966.4,4829.85 4005.77,4829.85
VBAT: H2.1 H15.1 | length 196.9
  Top Layer w10: H2.1@6410,4191.77 H15.1@6606.85,4191.77
VCC-3.3V: C26.1 C28.2 H12.2 R20.1 U6.5 U6.6 U7.5 U7.6 U10.2 U10.4 U12.4 U13.4 | length 6537.9
  Top Layer w10: R20.1@3359.66,5121.77 3505,5121.77 v1(3540,5086.77) ; v1(4125,3952.99) 4128.11,3956.1 U13.4@4128.11,4039.97
  Top Layer w20: U12.4@3493.11,4039.97 3493.11,4184.89 3585,4276.77 v1(3629.13,4276.77)
  Bottom Layer w10: U7.6@3592.8,4331.53 3595,4329.33 v1(3595,4276.77) ; 3617,4276.77 3618.39,4278.17 U7.5@3618.39,4331.53
  Bottom Layer w15: U6.6@3567.2,5067.01 3567.93,5066.29 3567.93,4993.85 3575,4986.77 4992.44,4986.77 v1@5246.83,5241.16
  Bottom Layer w30: 3617,4276.77 v1(3629.13,4276.77) 3729.99,4276.77 3760,4306.79 ; v1(4125,3952.99) 4103.79,3931.77 3870,3931.77 3760,4041.77 3760,4306.79 ; H12.2@4671.85,6096.77 4671.85,5874.92 5246.83,5299.94 5246.83,5241.16 v1(5246.83,5151.77) 5246.83,5008.6 5095,4856.77 4390,4856.77 3906.33,4373.1 3791.33,4373.1 3760,4341.77 3760,4306.79
  other v1: 4125,4036.77 3540,5049.45 5247.61,5197.83 5247.44,5241.77
VCC-5V: C24.1 C27.2 C32.1 C37.1 H10.3 H14.3 L1.2 R21.2 R24.1 U10.3 | length 3657.5
  Top Layer w10: R21.2@5044.66,5791.77 5102.99,5733.44 L1.2@5102.99,5656.77
  Top Layer w20: C37.1@5255,5644.09 5422.68,5644.09 5475,5591.77 5475,4530.32 H14.3@5613.54,4391.77 H10.3@5810.39,4391.77
  Bottom Layer w10: v1(3359.66,5221.77) 4610,5221.77 4745,5356.77 5085,5356.77 v1(5100,5341.77)
VIN: 
VIN_12V: C35.1 P3.1 R25.2 SW1.3 | length 140.2
  Top Layer w10: R25.2@3408.49,5764.3 3415,5770.8 3415,5901.77
pads on no net: C1.2 C3.1 C33.1 C34.1 C38.1 R23.1 SW1.1 SW1.2 U1.4 U1.11 U6.1 U7.1 U11.2 U11.3 U11.5 U11.7 U12.5 U12.6 U13.5 U13.6
copper on no net: | length 973.4
  Top Layer w10: 3359,5321.97 3458.8,5421.77 3800,5421.77 ; v1(3815,4648.93) 3815,4666.77 3829.46,4681.23 3873.26,4681.23
  Bottom Layer w30: v1(3725,4861.77) v1(3751.32,4861.77) v1(3778.02,4861.77) v1(3806.29,4861.77) 3865,4861.77 3875,4851.77 3875,4708.93 v1(3815,4648.93) v1@3815,4621.77
  other v1: 3815,4616.77
  other v3: 3351.22,3474.41 6445,3474.41 3351.22,6382.99 6445,6382.99
  other v4: 4423.43,4701.1 5320.28,4701.1 4423.43,6048.35
  other v5: 5320.28,6048.35

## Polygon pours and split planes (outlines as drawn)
M0_EN on Bottom Layer (solid, remove dead copper, pour order 4): 4070.54,4901.77 4190,4901.77 4200,4891.77 4200,4781.77 4190,4771.77 4060,4771.77 4055,4776.77 4055,4886.23
PGND on Top Layer (solid, remove dead copper): 3000,6881.77 3010,6111.77 3010,3000 4325,3711.77 4325,6141.77
GND on Top Layer (solid, remove dead copper, pour order 2): 4335,6151.77 6735,6746.77 6775,3141.77 4335,3711.77
PGND on Bottom Layer (solid, remove dead copper, pour order 6): 3000,6881.77 3002.5,6104.27 3010,3013.72 4317.5,3714.27 4317.5,6144.27
GND on Bottom Layer (solid, remove dead copper, pour order 8): 4328.48,6147.72 6740,6736.77 6765,3116.77 6625,3186.77 4343.48,3712.72 4328.48,3727.72

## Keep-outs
Board Outline Layer:
  lines w10: 3118.17,3486.77 3118.17,6131.04 ; 3118.17,6106.51 3115,6382.99 cw(c3351.22,6382.99) 3351.22,6619.22 cw(c3351.22,6382.99) 3587.44,6382.99 ccw(c3827.06,6386.02) 3826.13,6146.38 ; 3120,3486.77 ccw(c3356.22,3486.77) 3356.22,3250.55 ccw(c3356.22,3486.77) 3592.44,3486.77 cw(c3818.45,3492.16) 3823.12,3718.19 ; 3818.12,3718.19 5963.51,3718.19 ; 3818.84,6146.38 5967.35,6146.38 ; 5964.43,3718.19 cw(c5963.51,3478.56) 6203.13,3481.58 ccw(c6439.35,3481.58) 6439.35,3245.36 ccw(c6439.35,3481.58) 6675.57,3481.58 ; 5965,6148.72 ccw(c5971.88,6379.29) 6202.56,6378.72 cw(c6438.78,6378.72) 6438.78,6614.94 cw(c6438.78,6378.72) 6675,6378.72 6675,3566.77 ; 6675,3472.95 6675,3578.65

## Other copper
Top Layer:
  drawing of 218 lines, arcs and shapes, not listed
